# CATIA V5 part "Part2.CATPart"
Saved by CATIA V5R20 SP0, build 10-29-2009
Part number: Part2
Bounding box of the stored display mesh (mm): x 0 to 0, y 0 to 28.284, z 20 to 48.284
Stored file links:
  C:\Documents and Settings\Media\Escritorio\GATO_ALAMBRICO\Part2.CATPart
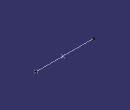
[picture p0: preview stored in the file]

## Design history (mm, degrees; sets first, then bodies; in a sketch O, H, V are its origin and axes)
Set1
  Point1: (0, 0, 0), relative to DatumPoint1
  DatumPoint1
  Line1: type Angle, RefPoint Point1, Curve Line2, Support yz-plane, Start 0, End 40, Angle -45
  Line2: stored without definition
  Point2: type OnCurve, Support Line1, Length 18.645
Body1 (main body)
